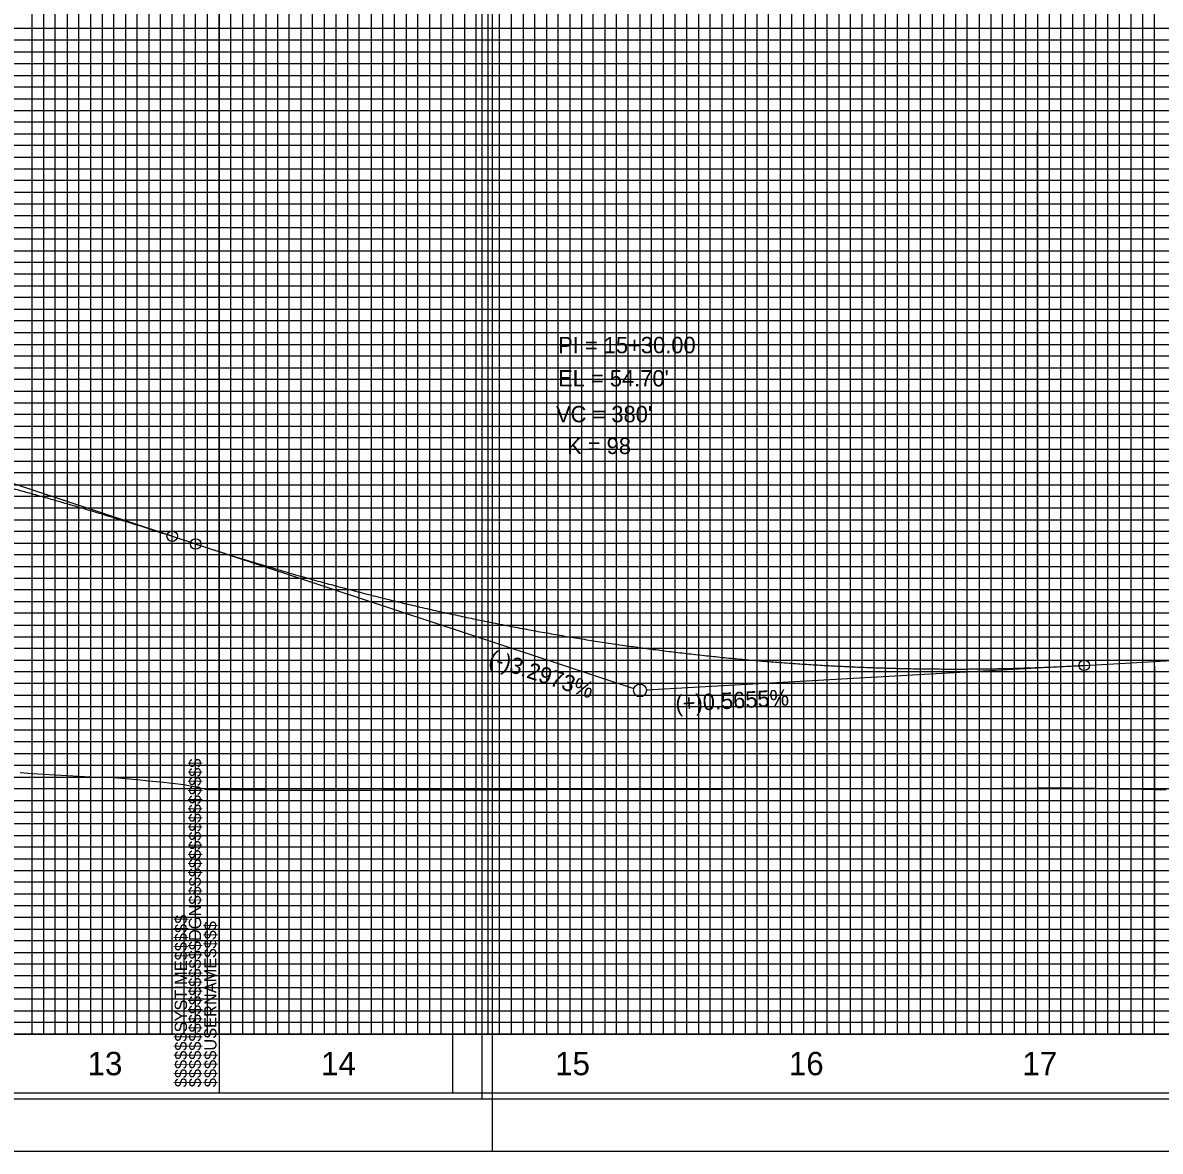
# Model space of a CAD drawing. Extents: x 2345490 to 2436403, y 465165 to 573888.
# Drawn here: x 2412161.4 to 2412647.8, y 502766 to 503248.5 of the extents above; entities that cross this region are included whole.
import ezdxf

# ---------------------------------------------------------------- set-up
doc = ezdxf.new("R2010")
doc.units = 0
for name, color, linetype in [('Old_Level_1', 7, 'Continuous'), ('Old_Level_18', 7, 'Continuous'), ('Old_Level_2', 7, 'Continuous'), ('Old_Level_40', 7, 'Continuous'), ('Old_Level_41', 7, 'Continuous'), ('Old_Level_42', 7, 'Continuous'), ('Old_Level_43', 7, 'Continuous'), ('Old_Level_50', 7, 'Continuous'), ('Old_Level_51', 7, 'Continuous'), ('Old_Level_63', 7, 'Continuous')]:
    doc.layers.add(name, color=color, linetype=linetype)

msp = doc.modelspace()

# ---------------------------------------------------------------- linework, layer by layer
at = {"layer": 'Old_Level_1'}
for points in [[(2412160.325, 502927.86625), (2412165.325, 502927.51925), (2412170.325, 502927.211), (2412175.325, 502926.905), (2412180.325, 502926.6015), (2412185.325, 502926.3005), (2412190.325, 502926.0735), (2412195.325, 502925.93275), (2412200.325, 502925.8425), (2412205.325, 502925.3515), (2412210.325, 502924.85775), (2412215.325, 502924.36125), (2412220.325, 502923.86225), (2412225.325, 502923.3605), (2412230.325, 502922.856), (2412235.325, 502921.7915), (2412240.325, 502920.69875), (2412245.325, 502920.58), (2412250.325, 502920.546), (2412255.325, 502920.51325), (2412260.325, 502920.48175), (2412265.325, 502920.45225), (2412270.325, 502920.432), (2412275.325, 502920.413), (2412280.325, 502920.395), (2412285.325, 502920.3715), (2412290.325, 502920.3475), (2412295.325, 502920.3245), (2412300.325, 502920.30775), (2412305.325, 502920.35975), (2412310.325, 502920.41225), (2412315.325, 502920.4655), (2412320.325, 502920.5195), (2412325.325, 502920.53825), (2412330.325, 502920.5445), (2412335.325, 502920.55175), (2412340.325, 502920.5525), (2412345.325, 502920.55225), (2412350.325, 502920.55275), (2412355.325, 502920.55375), (2412360.325, 502920.5555), (2412365.325, 502920.55225), (2412370.325, 502920.5475), (2412375.325, 502920.55575), (2412380.325, 502920.61125), (2412385.325, 502920.667), (2412390.325, 502920.72325), (2412395.325, 502920.7795)], [(2412395.325, 502920.7795), (2412400.325, 502920.8365), (2412405.325, 502920.853), (2412410.325, 502920.8535), (2412415.325, 502920.85175), (2412420.325, 502920.84475), (2412425.325, 502920.83825), (2412430.325, 502920.832), (2412435.325, 502920.82625), (2412440.325, 502920.821), (2412445.325, 502920.816), (2412450.325, 502920.8115), (2412455.325, 502920.80725), (2412460.325, 502920.8405), (2412465.325, 502920.875), (2412470.325, 502920.90975), (2412475.325, 502920.9445), (2412480.325, 502920.9795), (2412485.325, 502920.992), (2412490.325, 502920.9945), (2412495.325, 502920.99725), (2412500.325, 502921.002), (2412505.325, 502921.019), (2412510.325, 502921.03625), (2412515.325, 502921.0535), (2412520.325, 502921.07075), (2412525.325, 502921.07275), (2412530.325, 502921.066), (2412535.325, 502921.05925), (2412540.325, 502921.0525), (2412545.325, 502921.046), (2412550.325, 502921.0395), (2412555.325, 502921.033), (2412560.325, 502921.0265), (2412565.325, 502921.0445), (2412570.325, 502921.08625), (2412575.325, 502921.128), (2412580.325, 502921.16975), (2412585.325, 502921.21125), (2412590.325, 502921.253), (2412595.325, 502921.29475), (2412600.325, 502921.3295), (2412605.325, 502921.3325), (2412610.325, 502921.303), (2412615.325, 502921.27375), (2412620.325, 502921.2115), (2412625.325, 502921.107), (2412630.325, 502921.00125), (2412635.325, 502920.894), (2412640.325, 502920.7855), (2412645.325, 502920.676), (2412650.325, 502920.62725)]]:
    msp.add_lwpolyline(points, dxfattribs=at)
at = {"layer": 'Old_Level_18'}
msp.add_line((2412245.325, 502790.981), (2412245.325, 502790.981), dxfattribs=at)
msp.add_line((2412245.325, 502790.981), (2412245.325, 502790.981), dxfattribs=at)
for points in [[(2412345.325, 503840.981), (2410845.325, 503840.981), (2410845.325, 502790.981), (2412345.325, 502790.981)], [(2413745.325, 503840.981), (2412245.325, 503840.981), (2412245.325, 502790.981), (2413745.325, 502790.981)]]:
    msp.add_lwpolyline(points, close=True, dxfattribs=at)
at = {"layer": 'Old_Level_2'}
for p, q in [((2412225.325, 503028.927), (2412057.93675, 503084.12)), ((2412225.325, 503028.927), (2412235.325, 503025.62975)), ((2412235.325, 503025.62975), (2412422.7135, 502963.84225)), ((2412615.325, 502973.726), (2412655.325, 502975.988)), ((2412615.325, 502973.726), (2412428.07075, 502963.1365))]:
    msp.add_line(p, q, dxfattribs=at)
for centre, radius in [((2412225.325, 503028.927), 2.25), ((2412235.325, 503025.62975), 2.25), ((2412615.325, 502973.726), 2.25), ((2412425.325, 502962.981), 2.75)]:
    msp.add_circle(centre, radius, dxfattribs=at)
for points in [[(2411885.325, 503090.1755), (2411892.125, 503089.9475), (2411898.925, 503089.67875), (2411905.725, 503089.36925), (2411912.525, 503089.019), (2411919.325, 503088.628), (2411926.125, 503088.1965), (2411932.925, 503087.72425), (2411939.725, 503087.21125), (2411946.525, 503086.65775), (2411953.325, 503086.0635), (2411960.125, 503085.4285), (2411966.925, 503084.75275), (2411973.725, 503084.03625), (2411980.525, 503083.27925), (2411987.325, 503082.4815), (2411994.125, 503081.643), (2412000.925, 503080.764), (2412007.725, 503079.84425), (2412014.525, 503078.88375), (2412021.325, 503077.8825), (2412028.125, 503076.8405), (2412034.925, 503075.758), (2412041.725, 503074.63475), (2412048.525, 503073.47075), (2412055.325, 503072.26625), (2412062.125, 503071.021), (2412068.925, 503069.735), (2412075.725, 503068.40825), (2412082.525, 503067.04075), (2412089.325, 503065.63275), (2412096.125, 503064.184), (2412102.925, 503062.6945), (2412109.725, 503061.1645), (2412116.525, 503059.59375), (2412123.325, 503057.98225), (2412130.125, 503056.33), (2412136.925, 503054.637), (2412143.725, 503052.9035), (2412150.525, 503051.12925), (2412157.325, 503049.31425), (2412164.125, 503047.45875), (2412170.925, 503045.56225), (2412177.725, 503043.62525), (2412184.525, 503041.64775), (2412191.325, 503039.62925), (2412198.125, 503037.57025), (2412204.925, 503035.4705), (2412211.725, 503033.33), (2412218.525, 503031.149), (2412225.325, 503028.927)], [(2412235.325, 503025.62975), (2412242.925, 503023.15325), (2412250.525, 503020.73525), (2412258.125, 503018.37625), (2412265.725, 503016.07575), (2412273.325, 503013.834), (2412280.925, 503011.651), (2412288.525, 503009.52675), (2412296.125, 503007.461), (2412303.725, 503005.45425), (2412311.325, 503003.506), (2412318.925, 503001.6165), (2412326.525, 502999.786), (2412334.125, 502998.014), (2412341.725, 502996.3005), (2412349.325, 502994.646), (2412356.925, 502993.05025), (2412364.525, 502991.513), (2412372.125, 502990.0345), (2412379.725, 502988.61475), (2412387.325, 502987.25375), (2412394.925, 502985.9515), (2412402.525, 502984.708), (2412410.125, 502983.523), (2412417.725, 502982.397), (2412425.325, 502981.3295), (2412432.925, 502980.32075), (2412440.525, 502979.37075), (2412448.125, 502978.4795), (2412455.725, 502977.647), (2412463.325, 502976.873), (2412470.925, 502976.158), (2412478.525, 502975.5015), (2412486.125, 502974.90375), (2412493.725, 502974.36475), (2412501.325, 502973.8845), (2412508.925, 502973.463), (2412516.525, 502973.1), (2412524.125, 502972.796), (2412531.725, 502972.5505), (2412539.325, 502972.36375), (2412546.925, 502972.23575), (2412554.525, 502972.1665), (2412562.125, 502972.156), (2412569.725, 502972.204), (2412577.325, 502972.311), (2412584.925, 502972.4765), (2412592.525, 502972.70075), (2412600.125, 502972.98375), (2412607.725, 502973.3255), (2412615.325, 502973.726)]]:
    msp.add_spline(points, degree=3, dxfattribs=at)
at = {"layer": 'Old_Level_40'}
msp.add_line((2412245.325, 502790.981), (2412245.325, 502790.981), dxfattribs=at)
msp.add_line((2412245.325, 502790.981), (2412245.325, 502790.981), dxfattribs=at)
msp.add_line((2412245.325, 502790.981), (2412245.325, 502790.981), dxfattribs=at)
msp.add_line((2412245.325, 502790.981), (2412245.325, 502790.981), dxfattribs=at)
at = {"layer": 'Old_Level_41'}
for p, q in [((2412345.325, 502815.981), (2410845.325, 502815.981)), ((2413745.325, 502815.981), (2412245.325, 502815.981))]:
    msp.add_line(p, q, dxfattribs=at)
for points in [[(2412295.325, 503840.981), (2412295.325, 502815.981), (2412345.325, 502815.981), (2412345.325, 503840.981)], [(2412320.325, 502815.981), (2412320.325, 503840.981)], [(2412370.325, 503840.981), (2412370.325, 502815.981), (2412420.325, 502815.981), (2412420.325, 503840.981)], [(2412395.325, 503840.981), (2412395.325, 502815.981), (2412445.325, 502815.981), (2412445.325, 503840.981)], [(2412470.325, 503840.981), (2412470.325, 502815.981), (2412520.325, 502815.981), (2412520.325, 503840.981)], [(2412495.325, 503840.981), (2412495.325, 502815.981), (2412545.325, 502815.981), (2412545.325, 503840.981)], [(2412570.325, 503840.981), (2412570.325, 502815.981), (2412620.325, 502815.981), (2412620.325, 503840.981)], [(2412595.325, 503840.981), (2412595.325, 502815.981), (2412645.325, 502815.981), (2412645.325, 503840.981)], [(2412170.325, 503703.431), (2412170.325, 502815.981), (2412220.325, 502815.981), (2412220.325, 503703.431)], [(2412270.325, 503703.431), (2412270.325, 502815.981)], [(2412345.325, 503240.981), (2410845.325, 503240.981), (2410845.325, 503190.981), (2412345.325, 503190.981)], [(2413745.325, 503240.981), (2412245.325, 503240.981), (2412245.325, 503190.981), (2413745.325, 503190.981)], [(2412345.325, 503165.981), (2410845.325, 503165.981), (2410845.325, 503215.981), (2412345.325, 503215.981)], [(2413745.325, 503165.981), (2412245.325, 503165.981), (2412245.325, 503215.981), (2413745.325, 503215.981)], [(2412345.325, 503140.981), (2410845.325, 503140.981), (2410845.325, 503090.981), (2412345.325, 503090.981)], [(2413745.325, 503140.981), (2412245.325, 503140.981), (2412245.325, 503090.981), (2413745.325, 503090.981)], [(2412345.325, 503065.981), (2410845.325, 503065.981), (2410845.325, 503115.981), (2412345.325, 503115.981)], [(2413745.325, 503065.981), (2412245.325, 503065.981), (2412245.325, 503115.981), (2413745.325, 503115.981)], [(2412345.325, 503040.981), (2410845.325, 503040.981), (2410845.325, 502990.981), (2412345.325, 502990.981)], [(2413745.325, 503040.981), (2412245.325, 503040.981), (2412245.325, 502990.981), (2413745.325, 502990.981)], [(2412345.325, 502940.981), (2410845.325, 502940.981), (2410845.325, 502890.981), (2412345.325, 502890.981)], [(2413745.325, 502940.981), (2412245.325, 502940.981), (2412245.325, 502890.981), (2413745.325, 502890.981)], [(2412345.325, 502865.981), (2410845.325, 502865.981), (2410845.325, 502915.981), (2412345.325, 502915.981)], [(2413745.325, 502865.981), (2412245.325, 502865.981), (2412245.325, 502915.981), (2413745.325, 502915.981)], [(2412345.325, 502840.981), (2410845.325, 502840.981)], [(2413745.325, 502840.981), (2412245.325, 502840.981)], [(2412282.825, 502790.981), (2412282.825, 502790.981)]]:
    msp.add_lwpolyline(points, dxfattribs=at)
at = {"layer": 'Old_Level_42'}
for points in [[(2412195.325, 503703.431), (2412195.325, 502815.981), (2412245.325, 502815.981), (2412245.325, 503703.431)], [(2412295.325, 503703.431), (2412295.325, 502815.981), (2412345.325, 502815.981)], [(2412345.325, 502965.981), (2410845.325, 502965.981), (2410845.325, 503015.981), (2412345.325, 503015.981)], [(2413745.325, 502965.981), (2412245.325, 502965.981), (2412245.325, 503015.981), (2413745.325, 503015.981)]]:
    msp.add_lwpolyline(points, dxfattribs=at)
at = {"layer": 'Old_Level_43'}
for points in [[(2412300.325, 503840.981), (2412300.325, 502815.981), (2412305.325, 502815.981), (2412305.325, 503840.981)], [(2412310.325, 503840.981), (2412310.325, 502815.981), (2412315.325, 502815.981), (2412315.325, 503840.981)], [(2412325.325, 503840.981), (2412325.325, 502815.981), (2412330.325, 502815.981), (2412330.325, 503840.981)], [(2412335.325, 503840.981), (2412335.325, 502815.981), (2412340.325, 502815.981), (2412340.325, 503840.981)], [(2412350.325, 503840.981), (2412350.325, 502815.981), (2412355.325, 502815.981), (2412355.325, 503840.981)], [(2412360.325, 503840.981), (2412360.325, 502815.981), (2412365.325, 502815.981), (2412365.325, 503840.981)], [(2412375.325, 503840.981), (2412375.325, 502815.981), (2412380.325, 502815.981), (2412380.325, 503840.981)], [(2412385.325, 503840.981), (2412385.325, 502815.981), (2412390.325, 502815.981), (2412390.325, 503840.981)], [(2412400.325, 503840.981), (2412400.325, 502815.981), (2412405.325, 502815.981), (2412405.325, 503840.981)], [(2412410.325, 503840.981), (2412410.325, 502815.981), (2412415.325, 502815.981), (2412415.325, 503840.981)], [(2412425.325, 503840.981), (2412425.325, 502815.981), (2412430.325, 502815.981), (2412430.325, 503840.981)], [(2412435.325, 503840.981), (2412435.325, 502815.981), (2412440.325, 502815.981), (2412440.325, 503840.981)], [(2412450.325, 503840.981), (2412450.325, 502815.981), (2412455.325, 502815.981), (2412455.325, 503840.981)], [(2412460.325, 502815.981), (2412465.325, 502815.981), (2412465.325, 503840.981)], [(2412460.325, 503840.981), (2412460.325, 502815.981)], [(2412475.325, 503840.981), (2412475.325, 502815.981), (2412480.325, 502815.981), (2412480.325, 503840.981)], [(2412485.325, 503840.981), (2412485.325, 502815.981), (2412490.325, 502815.981), (2412490.325, 503840.981)], [(2412500.325, 503840.981), (2412500.325, 502815.981), (2412505.325, 502815.981), (2412505.325, 503840.981)], [(2412510.325, 503840.981), (2412510.325, 502815.981), (2412515.325, 502815.981), (2412515.325, 503840.981)], [(2412525.325, 503840.981), (2412525.325, 502815.981), (2412530.325, 502815.981), (2412530.325, 503840.981)], [(2412535.325, 503840.981), (2412535.325, 502815.981), (2412540.325, 502815.981), (2412540.325, 503840.981)], [(2412550.325, 503840.981), (2412550.325, 502815.981), (2412555.325, 502815.981), (2412555.325, 503840.981)], [(2412560.325, 503840.981), (2412560.325, 502815.981), (2412565.325, 502815.981), (2412565.325, 503840.981)], [(2412575.325, 503840.981), (2412575.325, 502815.981), (2412580.325, 502815.981), (2412580.325, 503840.981)], [(2412585.325, 503840.981), (2412585.325, 502815.981), (2412590.325, 502815.981), (2412590.325, 503840.981)], [(2412600.325, 503840.981), (2412600.325, 502815.981), (2412605.325, 502815.981), (2412605.325, 503840.981)], [(2412610.325, 503840.981), (2412610.325, 502815.981), (2412615.325, 502815.981), (2412615.325, 503840.981)], [(2412625.325, 503840.981), (2412625.325, 502815.981), (2412640.325, 502815.981), (2412640.325, 503840.981)], [(2412630.325, 503840.981), (2412630.325, 502815.981), (2412635.325, 502815.981), (2412635.325, 503840.981)], [(2412630.325, 503840.381), (2412630.325, 502815.981), (2412635.325, 502815.981), (2412635.325, 503840.381)], [(2412165.325, 503703.431), (2412165.325, 502815.981), (2412175.325, 502815.981), (2412175.325, 503703.431)], [(2412180.325, 503703.431), (2412180.325, 502815.981), (2412185.325, 502815.981), (2412185.325, 503703.431)], [(2412190.325, 503703.431), (2412190.325, 502815.981), (2412200.325, 502815.981), (2412200.325, 503703.431)], [(2412205.325, 503703.431), (2412205.325, 502815.981), (2412210.325, 502815.981), (2412210.325, 503703.431)], [(2412215.325, 503703.431), (2412215.325, 502815.981), (2412225.325, 502815.981), (2412225.325, 503703.431)], [(2412230.325, 503703.431), (2412230.325, 502815.981)], [(2412230.325, 502815.981), (2412235.325, 502815.981), (2412235.325, 503703.431)], [(2412240.325, 503703.431), (2412240.325, 502815.981), (2412250.325, 502815.981), (2412250.325, 503703.431)], [(2412255.325, 503703.431), (2412255.325, 502815.981), (2412260.325, 502815.981), (2412260.325, 503703.431)], [(2412265.325, 503703.431), (2412265.325, 502815.981), (2412275.325, 502815.981), (2412275.325, 503703.431)], [(2412280.325, 503703.431), (2412280.325, 502815.981), (2412285.325, 502815.981), (2412285.325, 503703.431)], [(2412290.325, 503703.431), (2412290.325, 502815.981), (2412300.325, 502815.981)], [(2412295.325, 503245.981), (2410895.325, 503245.981), (2410895.325, 503235.981), (2412295.325, 503235.981)], [(2413695.325, 503245.981), (2412295.325, 503245.981), (2412295.325, 503235.981), (2413695.325, 503235.981)], [(2412295.325, 503230.981), (2410895.325, 503230.981), (2410895.325, 503225.981), (2412295.325, 503225.981)], [(2413695.325, 503230.981), (2412295.325, 503230.981), (2412295.325, 503225.981), (2413695.325, 503225.981)], [(2412295.325, 503220.981), (2410895.325, 503220.981), (2410895.325, 503210.981), (2412295.325, 503210.981)], [(2413695.325, 503220.981), (2412295.325, 503220.981), (2412295.325, 503210.981), (2413695.325, 503210.981)], [(2412295.325, 503205.981), (2410895.325, 503205.981), (2410895.325, 503200.981), (2412295.325, 503200.981)], [(2413695.325, 503205.981), (2412295.325, 503205.981), (2412295.325, 503200.981), (2413695.325, 503200.981)], [(2412295.325, 503195.981), (2410895.325, 503195.981), (2410895.325, 503185.981), (2412295.325, 503185.981)], [(2413695.325, 503195.981), (2412295.325, 503195.981), (2412295.325, 503185.981), (2413695.325, 503185.981)], [(2412295.325, 503180.981), (2410895.325, 503180.981), (2410895.325, 503175.981), (2412295.325, 503175.981)], [(2413695.325, 503180.981), (2412295.325, 503180.981), (2412295.325, 503175.981), (2413695.325, 503175.981)], [(2412295.325, 503170.981), (2410895.325, 503170.981), (2410895.325, 503160.981), (2412295.325, 503160.981)], [(2413695.325, 503170.981), (2412295.325, 503170.981), (2412295.325, 503160.981), (2413695.325, 503160.981)], [(2412295.325, 503155.981), (2410895.325, 503155.981), (2410895.325, 503150.981), (2412295.325, 503150.981)], [(2413695.325, 503155.981), (2412295.325, 503155.981), (2412295.325, 503150.981), (2413695.325, 503150.981)], [(2412295.325, 503145.981), (2410895.325, 503145.981), (2410895.325, 503135.981), (2412295.325, 503135.981)], [(2413695.325, 503145.981), (2412295.325, 503145.981), (2412295.325, 503135.981), (2413695.325, 503135.981)], [(2412295.325, 503130.981), (2410895.325, 503130.981), (2410895.325, 503125.981), (2412295.325, 503125.981)], [(2413695.325, 503130.981), (2412295.325, 503130.981), (2412295.325, 503125.981), (2413695.325, 503125.981)], [(2412295.325, 503120.981), (2410895.325, 503120.981), (2410895.325, 503110.981), (2412295.325, 503110.981)], [(2413695.325, 503120.981), (2412295.325, 503120.981), (2412295.325, 503110.981), (2413695.325, 503110.981)], [(2412295.325, 503105.981), (2410895.325, 503105.981), (2410895.325, 503100.981), (2412295.325, 503100.981)], [(2413695.325, 503105.981), (2412295.325, 503105.981), (2412295.325, 503100.981), (2413695.325, 503100.981)], [(2412295.325, 503095.981), (2410895.325, 503095.981), (2410895.325, 503085.981), (2412295.325, 503085.981)], [(2413695.325, 503095.981), (2412295.325, 503095.981), (2412295.325, 503085.981), (2413695.325, 503085.981)], [(2412295.325, 503080.981), (2410895.325, 503080.981), (2410895.325, 503075.981), (2412295.325, 503075.981)], [(2413695.325, 503080.981), (2412295.325, 503080.981), (2412295.325, 503075.981), (2413695.325, 503075.981)], [(2412295.325, 503070.981), (2410895.325, 503070.981), (2410895.325, 503060.981), (2412295.325, 503060.981)], [(2413695.325, 503070.981), (2412295.325, 503070.981), (2412295.325, 503060.981), (2413695.325, 503060.981)], [(2412295.325, 503055.981), (2410895.325, 503055.981), (2410895.325, 503050.981), (2412295.325, 503050.981)], [(2413695.325, 503055.981), (2412295.325, 503055.981), (2412295.325, 503050.981), (2413695.325, 503050.981)], [(2412295.325, 503045.981), (2410895.325, 503045.981), (2410895.325, 503035.981), (2412295.325, 503035.981)], [(2413695.325, 503045.981), (2412295.325, 503045.981), (2412295.325, 503035.981), (2413695.325, 503035.981)], [(2412295.325, 503030.981), (2410895.325, 503030.981), (2410895.325, 503025.981), (2412295.325, 503025.981)], [(2413695.325, 503030.981), (2412295.325, 503030.981), (2412295.325, 503025.981), (2413695.325, 503025.981)], [(2412295.325, 503020.981), (2410895.325, 503020.981)], [(2413695.325, 503020.981), (2412295.325, 503020.981)], [(2410895.325, 503010.981), (2412295.325, 503010.981)], [(2412295.325, 503010.981), (2413695.325, 503010.981)], [(2412295.325, 503005.981), (2410895.325, 503005.981), (2410895.325, 503000.981), (2412295.325, 503000.981)], [(2413695.325, 503005.981), (2412295.325, 503005.981), (2412295.325, 503000.981), (2413695.325, 503000.981)], [(2412295.325, 502995.981), (2410895.325, 502995.981)], [(2413695.325, 502995.981), (2412295.325, 502995.981)], [(2410895.325, 502985.981), (2412295.325, 502985.981)], [(2412295.325, 502985.981), (2413695.325, 502985.981)], [(2412295.325, 502980.981), (2410895.325, 502980.981), (2410895.325, 502975.981), (2412295.325, 502975.981)], [(2413695.325, 502980.981), (2412295.325, 502980.981), (2412295.325, 502975.981), (2413695.325, 502975.981)], [(2412295.325, 502970.981), (2410895.325, 502970.981), (2410895.325, 502960.981), (2412295.325, 502960.981)], [(2413695.325, 502970.981), (2412295.325, 502970.981), (2412295.325, 502960.981), (2413695.325, 502960.981)], [(2412295.325, 502955.981), (2410895.325, 502955.981), (2410895.325, 502950.981), (2412295.325, 502950.981)], [(2413695.325, 502955.981), (2412295.325, 502955.981), (2412295.325, 502950.981), (2413695.325, 502950.981)], [(2412295.325, 502945.981), (2410895.325, 502945.981), (2410895.325, 502935.981), (2412295.325, 502935.981)], [(2413695.325, 502945.981), (2412295.325, 502945.981), (2412295.325, 502935.981), (2413695.325, 502935.981)], [(2412295.325, 502930.981), (2410895.325, 502930.981), (2410895.325, 502925.981), (2412295.325, 502925.981)], [(2413695.325, 502930.981), (2412295.325, 502930.981), (2412295.325, 502925.981), (2413695.325, 502925.981)], [(2412295.325, 502920.981), (2410895.325, 502920.981), (2410895.325, 502910.981), (2412295.325, 502910.981)], [(2413695.325, 502920.981), (2412295.325, 502920.981), (2412295.325, 502910.981), (2413695.325, 502910.981)], [(2412295.325, 502905.981), (2410895.325, 502905.981), (2410895.325, 502900.981), (2412295.325, 502900.981)], [(2413695.325, 502905.981), (2412295.325, 502905.981), (2412295.325, 502900.981), (2413695.325, 502900.981)], [(2412295.325, 502895.981), (2410895.325, 502895.981), (2410895.325, 502885.981), (2412295.325, 502885.981)], [(2413695.325, 502895.981), (2412295.325, 502895.981), (2412295.325, 502885.981), (2413695.325, 502885.981)], [(2412295.325, 502880.981), (2410895.325, 502880.981), (2410895.325, 502875.981), (2412295.325, 502875.981)], [(2413695.325, 502880.981), (2412295.325, 502880.981), (2412295.325, 502875.981), (2413695.325, 502875.981)], [(2412295.325, 502870.981), (2410895.325, 502870.981), (2410895.325, 502860.981), (2412295.325, 502860.981)], [(2413695.325, 502870.981), (2412295.325, 502870.981), (2412295.325, 502860.981), (2413695.325, 502860.981)], [(2412295.325, 502855.981), (2410895.325, 502855.981), (2410895.325, 502850.981), (2412295.325, 502850.981)], [(2413695.325, 502855.981), (2412295.325, 502855.981), (2412295.325, 502850.981), (2413695.325, 502850.981)], [(2412295.325, 502845.981), (2410895.325, 502845.981), (2410895.325, 502835.981), (2412295.325, 502835.981)], [(2413695.325, 502845.981), (2412295.325, 502845.981), (2412295.325, 502835.981), (2413695.325, 502835.981)], [(2412295.325, 502830.981), (2410895.325, 502830.981), (2410895.325, 502825.981), (2412295.325, 502825.981)], [(2413695.325, 502830.981), (2412295.325, 502830.981), (2412295.325, 502825.981), (2413695.325, 502825.981)], [(2412295.325, 502820.981), (2410895.325, 502820.981)], [(2413695.325, 502820.981), (2412295.325, 502820.981)]]:
    msp.add_lwpolyline(points, dxfattribs=at)
at = {"layer": 'Old_Level_50'}
for points in [[(2412357.825, 503843.531), (2410691.325, 503843.531), (2410691.325, 502788.431), (2412357.825, 502788.431)], [(2413757.825, 503843.531), (2412091.325, 503843.531), (2412091.325, 502788.431), (2413757.825, 502788.431)]]:
    msp.add_lwpolyline(points, close=True, dxfattribs=at)
at = {"layer": 'Old_Level_51'}
for points in [[(2412362.325, 503865.981), (2410678.325, 503865.981), (2410678.325, 502765.981), (2412362.325, 502765.981)], [(2413762.325, 503865.981), (2412078.325, 503865.981), (2412078.325, 502765.981), (2413762.325, 502765.981)]]:
    msp.add_lwpolyline(points, close=True, dxfattribs=at)
at = {"layer": 'Old_Level_63'}
for p, q in [((2412545.325, 502974.751), (2412545.325, 503201.93675)), ((2412595.325, 502976.781), (2412595.325, 503201.93675)), ((2412645.325, 502977.591), (2412645.325, 503201.93675)), ((2412645.325, 502973.371), (2412645.325, 502839.89625)), ((2412595.325, 502967.021), (2412595.325, 502839.89625)), ((2412545.325, 502957.681), (2412545.325, 502839.89625)), ((2410895.325, 502815.981), (2412874.915, 502815.981))]:
    msp.add_line(p, q, dxfattribs=at)

# ---------------------------------------------------------------- texts
at = {"layer": 'Old_Level_1'}
for s, p in [('13', (2412189.131, 502798.481)), ('16', (2412489.007, 502798.481)), ('14', (2412288.9735, 502798.481)), ('15', (2412389.066, 502798.481)), ('17', (2412588.8645, 502798.481))]:
    msp.add_text(s, height=10.000001, dxfattribs=at).set_placement(p)
at = {"layer": 'Old_Level_2'}
for s, height, p in [('PI = 15+30.00', 7.0000005, (2412390.32525, 503107.17375)), ("EL = 54.70'", 7.0000005, (2412390.325, 503092.981)), ("VC = 380'", 7.000001, (2412389.429, 503077.65675)), ('K = 98', 7.000001, (2412394.1735, 503064.0815))]:
    msp.add_text(s, height=height, dxfattribs=at).set_placement(p)
for s, rotation, p in [('(-)3.2973%', 341.751075, (2412360.13175, 502973.948)), ('(+)0.5655%', 3.2367278, (2412440.68125, 502953.83375))]:
    msp.add_text(s, height=7.000001, rotation=rotation, dxfattribs=at).set_placement(p)
at = {"layer": 'Old_Level_41'}
for s, p in [('$$$$$$$$$$$$$$$$DGN$$$$$$$$$$$$$$$$', (2412237.675, 502793.3435)), ('$$$$$$SYSTIME$$$$$', (2412231.625, 502793.3435)), ('$$$$USERNAME$$$$', (2412244.25, 502793.356))]:
    msp.add_text(s, height=5.25, rotation=90, dxfattribs=at).set_placement(p)

doc.saveas('drawing.dxf')
